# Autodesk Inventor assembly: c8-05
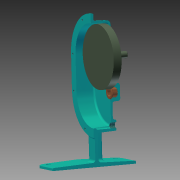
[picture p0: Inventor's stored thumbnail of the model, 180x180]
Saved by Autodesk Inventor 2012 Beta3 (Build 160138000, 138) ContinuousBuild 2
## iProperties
Created: 2010-12
Part Number: c8-05
Document SubType Name: Assembly
Designer: Thom Tremblay
Author: Thom Tremblay
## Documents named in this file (4)
- C:\Inventor 2012 Essentials\Assemblies\Chapter 8\c8-05.iam
- C:\Inventor 2012 Essentials\Content Center Files\en-US\ISO 2795  F\ISO 2795 - 10 x 14 x 10F.ipt
- C:\Inventor 2012 Essentials\Parts\Chapter 8\c8-11.ipt
- C:\Inventor 2012 Essentials\Assemblies\Chapter 8\Design Accelerators\Blank Input Shaft 1.iam
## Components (4 placed, 3 different names)
1. c8-11:1 — Insert:27, Insert:28
2. ISO 2795 (Flanged) 10 x 14 x 10:2 — Insert:27
3. ISO 2795 (Flanged) 10 x 14 x 10:3 — Insert:28, Insert:29
4. Blank Input Shaft 1:1 [sub-assembly] — Insert:29
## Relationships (3: Insert 3)
- Insert:27: c8-11:1 ↔ ISO 2795 (Flanged) 10 x 14 x 10:2
- Insert:28: c8-11:1 ↔ ISO 2795 (Flanged) 10 x 14 x 10:3
- Insert:29: ISO 2795 (Flanged) 10 x 14 x 10:3 ↔ Blank Input Shaft 1:1
